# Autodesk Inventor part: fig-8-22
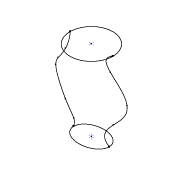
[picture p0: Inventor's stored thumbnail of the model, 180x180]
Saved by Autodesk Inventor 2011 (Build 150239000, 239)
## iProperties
Shininess: 64.0
Length Units: 11269
Angle Units: 11279
Time Units: 11290
Mass Units: 11283
Length Display Precision: 3
Angle Display Precision: 2
Compacted: True
Part Number: fig-8-22
Document SubType Name: Modeling
Created: 2002-12
Designer: deepak
Density: 1 g/cm^3
Density: 0.0
Volumn: 0.0
Area: 0.0
PropertySet Name: Model Information
Control State: 0
Master: False
Checked Out: False
Author: deepak
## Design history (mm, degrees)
sketch "Sketch1"
  geometry: 2 further points; 1 other entity
  constraints: 1 coincident, 3 other
workplane "Work Plane1"
workplane "Work Plane2"
sketch "Sketch3"
  geometry: C1 r 60 at (0, 0); 1 further point
  constraints: 1 centre point, 1 coincident, 1 other
sketch "Sketch4"
  geometry: 8 further points
  constraints: 8 other
sketch "Sketch5"
  geometry: 6 further points
  constraints: 6 other
sketch "Sketch6"
  geometry: 6 further points
  constraints: 6 other
  dimensions: "d20" = 35 distance of point (0, 0) point (-35, 0); "d21" = 0 vertical distance of point (0, 0) point (-35, 0); "d22" = 225 vertical distance of point (0, 0) point (-60, 225); "d23" = 60 horizontal distance of point (0, 0) point (-60, 225); "d24" = 100 horizontal distance of point (0, 0) point (-100, 125); "d25" = 125 vertical distance of point (0, 0) point (-100, 125)
other parameters: "d5" = 125
